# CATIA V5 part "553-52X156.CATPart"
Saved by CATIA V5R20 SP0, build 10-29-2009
Part number: 553-52X156
Definition: NONE
Nomenclature: 553-52X156
Source: Unknown
Description: 553-52X156
Bounding box of the stored display mesh (mm): x 0 to 156, y -35.5 to 35.5, z -35.5 to 35.5
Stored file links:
  C:\Users\Utente\Desktop\IO LAVORO\3D X SITO CF\X SITO\PLASTICA\553\553-52X156.CATPart
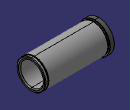
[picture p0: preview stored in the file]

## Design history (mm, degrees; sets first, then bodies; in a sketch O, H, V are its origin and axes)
Body1 "553-52X156" (main body)
  Solid1: solid without history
